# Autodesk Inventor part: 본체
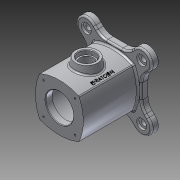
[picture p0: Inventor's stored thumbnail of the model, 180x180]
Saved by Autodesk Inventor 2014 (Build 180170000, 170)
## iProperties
Created: 2016-05
Part Number: 본체
Material: 알루미늄 6061
Document SubType Name: Modeling
Designer: Administrator
Density: 2.71 g/cm^3
Appearance: 알루미늄 - 평지
Mass: 1108.36 g
Surface Area: 864.931 cm^2
Volume: 408.988 cm^3
Author: Administrator
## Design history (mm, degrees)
sketch "스케치1"
  geometry: L1 (43, -43)-(-43, -43); L2 (-43, -43)-(-43, 43); L3 (-43, 43)-(43, 43); L4 (43, 43)-(43, -43); L5 (43, -43)-(-43, 43); L6 (-43, -43)-(43, 43); L7 (0, 43)-(0, -42.579); A1 r 50 centre (0, 0) between (35.355, 35.355) and (-35.355, 35.355); A2 r 85.579 centre (0, -42.579) between (35.355, 35.355) and (-35.355, 35.355); A3 r 85.579 centre (-42.579, 0) between (35.355, -35.355) and (35.355, 35.355); A4 r 90.136 centre (0, 47.557) between (-35.355, -35.355) and (35.355, -35.355); A5 r 85.579 centre (42.579, 0) between (-35.355, 35.355) and (-35.355, -35.355); 1 further point
  constraints: 14 end point, 14 point on circle, 5 centre point, 4 point on line, 3 parallel, 2 equal radius, 2 midpoint, 2 perpendicular, 1 coincident, 1 horizontal, 1 tangent
  dimensions: "d0" = 100 diameter of A1; "d1" = 86 distance of L2.end L3.end
extrude "돌출1" new body sketch "스케치1" stored distance "d2" = 98; taper "d3" = 0 deg
sketch "스케치3"
  geometry: L1 (-49, -49)-(49, -49); L2 (49, -49)-(49, 49); L3 (49, 49)-(-49, 49); L4 (-49, 49)-(-49, -49); L5 (-49, -49)-(49, 49); L6 (49, -49)-(-49, 49); L7 (0, 0)-(49.497, 49.497); L8 (35.239, 60.483)-(23.755, 49); L9 (60.483, 35.239)-(49, 23.755); L10 (-98, 0)-(98, 0) reference; A1 r 70 centre (0, 0) between (49.497, 49.497) and (35.239, 60.483); A2 r 18 centre (49.497, 49.497) between (35.239, 60.483) and (60.483, 35.239); 1 further point
  constraints: 18 end point, 5 point on circle, 4 parallel, 3 perpendicular, 2 centre point, 2 coincident, 2 midpoint, 2 point on line, 1 horizontal
  dimensions: "d16" = 140 diameter of A1; "d17" = 98 distance of L1.start L1.end; "d18" = 36 diameter of A2; "d19" = 45 deg angle of L10 L5 (derived)
extrude "돌출3" join sketch "스케치3" distance "d20" = 12; taper "d21" = 0 deg
extrude "돌출4" join sketch "스케치3" distance "d22" = 12; taper "d23" = 0 deg
sketch "스케치4"
  geometry: L1 (-49, 0)-(-37, 0); L2 (-37, 0)-(-37, -25); L3 (-37, -25)-(-49, -25); L4 (-49, -25)-(-49, 0); L5 (-37, 0)-(49, 0); L6 (49, 0)-(49, -35); L7 (49, -35)-(-37, -35); L8 (-37, -35)-(-37, 0); L9 (49, 0)-(61, 0); L10 (61, 0)-(61, -25); L11 (61, -25)-(49, -25); L12 (49, -25)-(49, 0); L13 (-49, 35.355)-(-49, -35.355) reference; 2 further points
  constraints: 24 end point, 6 parallel, 3 horizontal, 3 perpendicular, 2 equal length, 2 point on line, 1 midpoint
  dimensions: "d24" = 50 diameter of L3 L5; "d25" = 70 diameter of L7 L5; "d26" = 86 distance of L6.end L7.end; "d27" = 12 distance of L10.end L11.end
revolve "회전1" sketch "스케치4" stored, may be unused: angle "d28" = 90 deg
node "작업 평면1"
sketch "스케치5"
  geometry: C1 r 20 at (0, 0); 1 further point
  constraints: 1 centre point, 1 coincident
  dimensions: "d30" = 40 diameter of C1
extrude "돌출5" join sketch "스케치5" stored distance "d31" = 12; taper "d32" = 0 deg
hole "구멍1" diameter "d35" = 25; stored, may be unused: countersink angle "d39" = 90 deg, drill point angle "d41" = 118 deg; dims "d33" = 10, "d34" = 10, "d36" = 6, "d37" = 30, "d38" = 8, "d40" = 8
feature "면 기울기1" dims angle "d42" = 10 deg
sketch "스케치6"
  geometry: L1 (0, 0)-(28.284, 28.284); L2 (-94.496, 0)-(94.496, 0) reference
  constraints: 2 end point
  dimensions: "d43" = 45 deg angle of L2 L1; "d44" = 40 distance of L1.start L1.end
hole "구멍2" sketch "스케치6" at (28.284, 28.284) diameter "d45" = 3.242; stored, may be unused: countersink angle "d49" = 90 deg, drill point angle "d51" = 118 deg; dims "d46" = 7, "d47" = 10, "d48" = 8, "d50" = 10
sketch "스케치7"
  geometry: L1 (0, 0)-(49.497, 49.497); L2 (-94.496, 0)-(94.496, 0) reference; A1 r 18 centre (49.497, 49.497) between (60.483, 35.239) and (35.239, 60.483) reference
  constraints: 2 end point
  dimensions: "d55" = 45 deg angle of L2 L1; "d56" = 70 distance of L1.start L1.end
hole "구멍3" sketch "스케치7" at (49.497, 49.497) diameter "d57" = 10; stored, may be unused: countersink angle "d61" = 90 deg, drill point angle "d63" = 0 deg; dims "d58" = 7, "d59" = 18, "d60" = 4, "d62" = 10
chamfer "모따기1" distance "d67" = 1; stored, may be unused: second distance "d68" = 2, angle "d69" = 45 deg
fillet "모깎기1" dims "d70" = 3
fillet "모깎기2" dims "d71" = 25
sketch "스케치8"
  geometry: L1 (0, 0)-(-28.284, -28.284); L2 (-94.496, 0)-(94.496, 0) reference
  constraints: 2 end point
  dimensions: "d72" = 40 distance of L1.start L1.end; "d73" = 45 deg angle of L2 L1
hole "구멍4" sketch "스케치8" at (-28.284, -28.284) diameter "d74" = 3.242; stored, may be unused: countersink angle "d78" = 90 deg, drill point angle "d80" = 118 deg; dims "d75" = 7, "d76" = 18, "d77" = 4, "d79" = 10
fillet "모깎기3" dims "d84" = 3
fillet "모깎기4" dims "d85" = 3
fillet "모깎기5" dims "d86" = 3
fillet "모깎기6" dims "d87" = 3
node "작업 평면4"
sketch "스케치10"
  geometry: 2 further points
  constraints: 1 other
feature "엠보싱1" sketch "스케치10" dims "d17" = 98, "d93" = 0.5, "d94" = 0
node "솔리드1"
mirror "대칭1"
mirror "대칭2"
pattern_circular "원형 패턴1" dims angle "d53" = 360 deg
pattern_circular "원형 패턴2" dims angle "d65" = 360 deg
pattern_circular "원형 패턴3" dims angle "d82" = 360 deg
other parameters: "d29" = 55
